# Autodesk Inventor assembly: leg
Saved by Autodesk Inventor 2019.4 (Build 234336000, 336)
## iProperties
Created: 2020-09
Part Number: leg
Document SubType Name: Assembly
Designer: Administrator
Title: leg
Author: Administrator
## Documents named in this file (5)
- c:\worker\convert-fusion-r07\tmp\job-1\164\output\files\c50c4620-2026-4653-9277-f8972be5ac5a\leg_2.iam
- c:\worker\convert-fusion-r07\tmp\job-1\164\output\files\c50c4620-2026-4653-9277-f8972be5ac5a\legA.ipt
- c:\worker\convert-fusion-r07\tmp\job-1\164\output\files\c50c4620-2026-4653-9277-f8972be5ac5a\legB.ipt
- c:\worker\convert-fusion-r07\tmp\job-1\164\output\files\c50c4620-2026-4653-9277-f8972be5ac5a\legC.ipt
- c:\worker\convert-fusion-r07\tmp\job-1\164\output\files\c50c4620-2026-4653-9277-f8972be5ac5a\legD.ipt
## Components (4 placed, 4 different names)
1. legA:1
2. legB:1
3. legC:1
4. legD:1
